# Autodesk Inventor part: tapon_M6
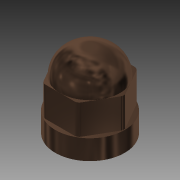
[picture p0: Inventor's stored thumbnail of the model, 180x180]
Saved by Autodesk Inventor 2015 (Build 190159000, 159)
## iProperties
Created: 2016-06
Part Number: tapon_M6
Material: Genérico
Document SubType Name: Modeling
Designer: Diego
Density: 1 g/cm^3
Appearance: Valor por defecto
Author: Diego
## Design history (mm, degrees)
sketch "Boceto1"
  geometry: C1 r 3.5 at (0, 0); 1 further point
  constraints: 1 centre point, 1 coincident
  dimensions: "d0" = 7 diameter of C1
extrude "Extrusión1" new body sketch "Boceto1" distance "d1" = 2; taper "d2" = 0 deg
sketch "Boceto2"
  geometry: L1 (-3.5, 0)-(-1.75, 3.031); L2 (-1.75, 3.031)-(1.75, 3.031); L3 (1.75, 3.031)-(3.5, 0); L4 (3.5, 0)-(1.75, -3.031); L5 (1.75, -3.031)-(-1.75, -3.031); L6 (-1.75, -3.031)-(-3.5, 0); A1 r 3.5 centre (0, 0) between (-3.5, 0) and (-1.75, 3.031) reference; 1 further point
  constraints: 12 end point, 6 point on circle
  dimensions: "d3" = 3.5 distance of L1.start L1.end; "d4" = 3.5 distance of L1.end L2.end; "d5" = 3.5 distance of L2.end L3.end; "d6" = 3.5 distance of L3.end L4.end; "d7" = 3.5 distance of L4.end L5.end
extrude "Extrusión2" join sketch "Boceto2" distance "d8" = 3; taper "d9" = 0 deg
sketch "Boceto3"
  geometry: C1 r 3.031 at (0, 0); 1 further point
  constraints: 1 centre point, 1 coincident
extrude "Extrusión3" join sketch "Boceto3" distance "d10" = 2.5; taper "d11" = 0 deg
fillet "Empalme1" dims "d12" = 2.5
fillet "Empalme2" dims "d13" = 0.5
node "Sólido1"
